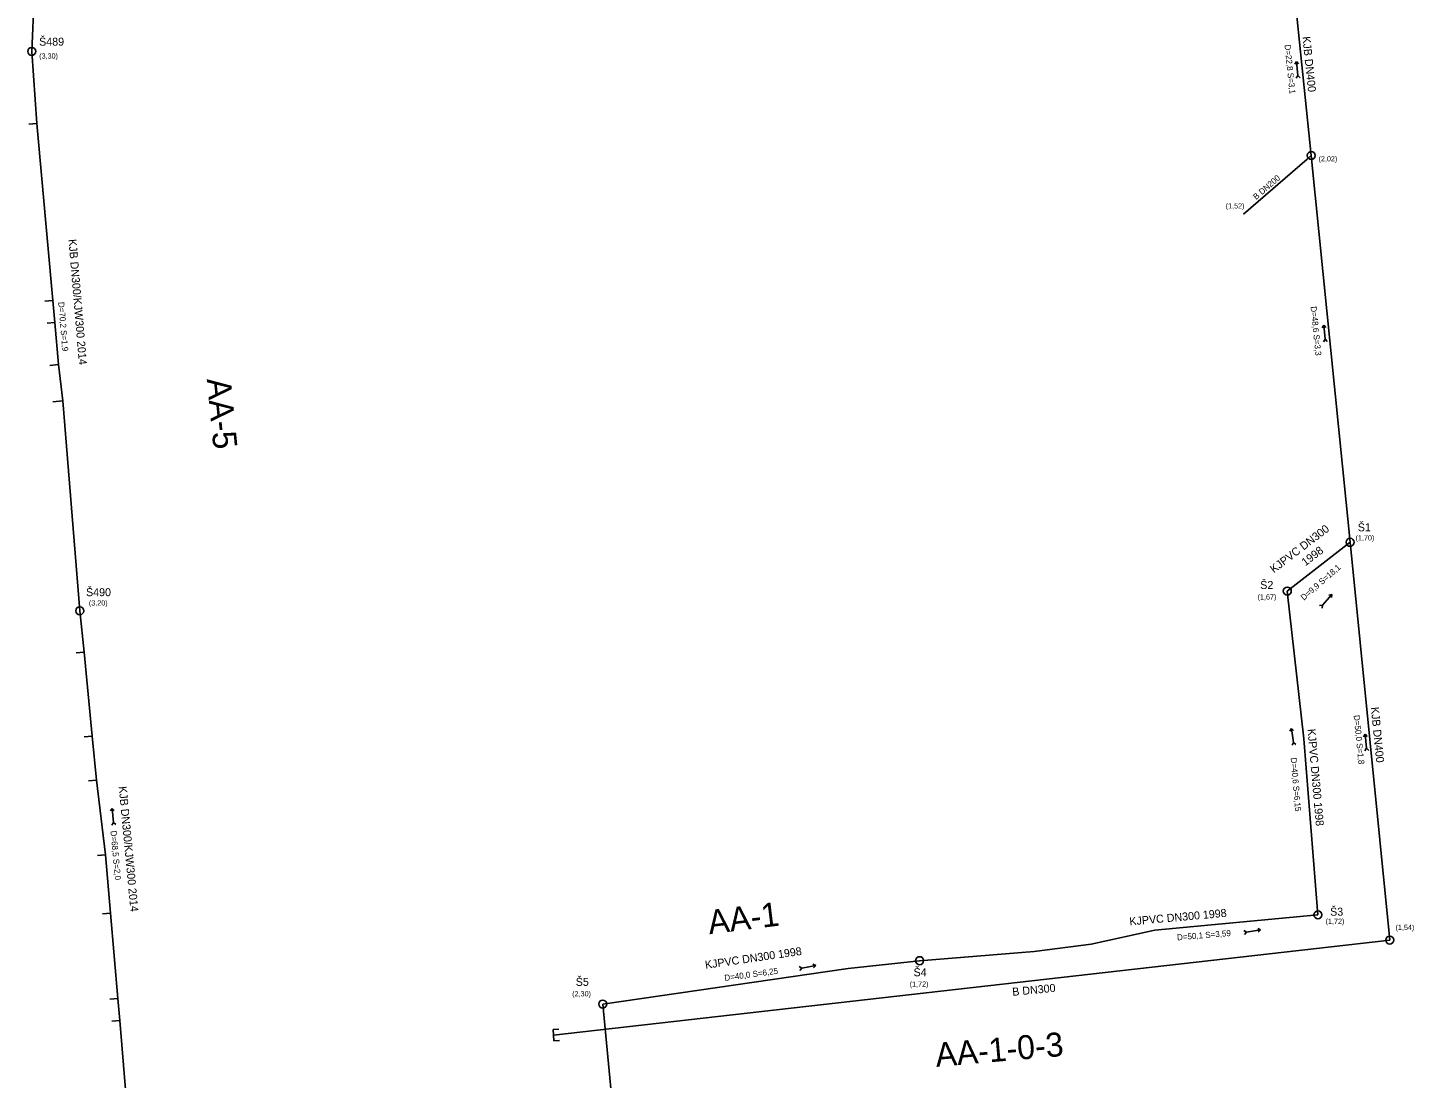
# Model space of a CAD drawing. Extents: x -539706 to -539225, y -1156458 to -1155912.
# Drawn here: x -539640.2 to -539467, y -1156258.9 to -1156127.6 of the extents above; entities that cross this region are included whole.
import ezdxf

# ---------------------------------------------------------------- set-up
doc = ezdxf.new("R2010")
doc.units = 0
for name, color, linetype in [('Vrstva 17', 7, 'Continuous'), ('Vrstva 23', 7, 'Continuous'), ('Vrstva 29', 7, 'Continuous'), ('Vrstva 39', 7, 'Continuous'), ('Vrstva 42', 7, 'Continuous'), ('Vrstva 46', 7, 'Continuous'), ('Vrstva 54', 7, 'Continuous'), ('Vrstva 57', 7, 'Continuous'), ('Vrstva 59', 7, 'Continuous'), ('Vrstva 60', 7, 'Continuous'), ('Vrstva 7', 7, 'Continuous'), ('Vrstva 8', 7, 'Continuous'), ('Vrstva 9', 7, 'Continuous')]:
    doc.layers.add(name, color=color, linetype=linetype)

msp = doc.modelspace()

# ---------------------------------------------------------------- linework, layer by layer
at = {"layer": 'Vrstva 17'}
for p, q in [((-539639.07, -1156139.54), (-539640.07, -1156139.62)), ((-539480.299, -1156144), (-539479.78, -1156143.55)), ((-539488.26, -1156150.9), (-539480.299, -1156144)), ((-539637.06, -1156161.68), (-539638.057, -1156161.764)), ((-539636.81, -1156164.42), (-539637.744, -1156164.497)), ((-539636.33, -1156169.69), (-539637.425, -1156169.783)), ((-539635.81, -1156174.22), (-539637.041, -1156174.324)), ((-539633.15, -1156205.63), (-539634.146, -1156205.714)), ((-539632.14, -1156216.11), (-539633.136, -1156216.194)), ((-539631.6, -1156221.64), (-539632.596, -1156221.724)), ((-539630.46, -1156230.94), (-539631.456, -1156231.024)), ((-539629.84, -1156238.25), (-539630.836, -1156238.334)), ((-539628.93, -1156248.9), (-539629.926, -1156248.984)), ((-539628.69, -1156251.67), (-539629.686, -1156251.754))]:
    msp.add_line(p, q, dxfattribs=at)
at = {"layer": 'Vrstva 23'}
msp.add_line((-539574.481, -1156253.5), (-539469.97, -1156241.61), dxfattribs=at)
at = {"layer": 'Vrstva 29'}
for centre in [(-539639.69, -1156130.54), (-539479.78, -1156143.55), (-539474.92, -1156191.9), (-539482.77, -1156197.99), (-539633.68, -1156200.46), (-539478.95, -1156238.46), (-539469.97, -1156241.61), (-539528.73, -1156244.19), (-539568.33, -1156249.61)]:
    msp.add_circle(centre, 0.5, dxfattribs=at)
at = {"layer": 'Vrstva 39'}
for p, q in [((-539481.835, -1156132.129), (-539481.634, -1156131.799)), ((-539481.454, -1156133.544), (-539481.634, -1156131.799)), ((-539481.373, -1156132.081), (-539481.634, -1156131.799)), ((-539481.658, -1156133.879), (-539481.454, -1156133.544)), ((-539481.184, -1156133.83), (-539481.454, -1156133.544)), ((-539478.427, -1156165.102), (-539478.225, -1156164.773)), ((-539478.052, -1156166.518), (-539478.225, -1156164.773)), ((-539477.966, -1156165.055), (-539478.225, -1156164.773)), ((-539478.257, -1156166.852), (-539478.052, -1156166.518)), ((-539477.783, -1156166.806), (-539478.052, -1156166.518)), ((-539478.382, -1156199.742), (-539477.214, -1156198.434)), ((-539477.593, -1156198.507), (-539477.214, -1156198.434)), ((-539477.246, -1156198.816), (-539477.214, -1156198.434)), ((-539478.767, -1156199.816), (-539478.382, -1156199.742)), ((-539478.412, -1156200.134), (-539478.382, -1156199.742)), ((-539482.438, -1156215.509), (-539482.255, -1156215.169)), ((-539481.982, -1156216.902), (-539482.255, -1156215.169)), ((-539481.979, -1156215.437), (-539482.255, -1156215.169)), ((-539473.24, -1156216.21), (-539473.037, -1156215.882)), ((-539472.865, -1156217.627), (-539473.037, -1156215.882)), ((-539472.778, -1156216.164), (-539473.037, -1156215.882)), ((-539482.168, -1156217.247), (-539481.982, -1156216.902)), ((-539481.697, -1156217.174), (-539481.982, -1156216.902)), ((-539473.071, -1156217.961), (-539472.865, -1156217.627)), ((-539472.597, -1156217.915), (-539472.865, -1156217.627)), ((-539629.829, -1156225.48), (-539629.625, -1156225.152)), ((-539629.462, -1156226.899), (-539629.625, -1156225.152)), ((-539629.368, -1156225.436), (-539629.625, -1156225.152)), ((-539629.67, -1156227.232), (-539629.462, -1156226.899)), ((-539629.195, -1156227.188), (-539629.462, -1156226.899)), ((-539488.207, -1156240.438), (-539487.86, -1156240.622)), ((-539487.86, -1156240.622), (-539486.129, -1156240.338)), ((-539486.471, -1156240.157), (-539486.129, -1156240.338)), ((-539486.395, -1156240.615), (-539486.129, -1156240.338)), ((-539488.13, -1156240.909), (-539487.86, -1156240.622)), ((-539543.79, -1156244.931), (-539543.44, -1156245.108)), ((-539543.704, -1156245.4), (-539543.44, -1156245.108)), ((-539543.44, -1156245.108), (-539541.715, -1156244.788)), ((-539542.06, -1156244.614), (-539541.715, -1156244.788)), ((-539541.975, -1156245.07), (-539541.715, -1156244.788))]:
    msp.add_line(p, q, dxfattribs=at)
at = {"layer": 'Vrstva 42'}
for p, q in [((-539574.532, -1156252.796), (-539573.829, -1156252.746)), ((-539574.43, -1156254.204), (-539574.532, -1156252.796)), ((-539574.43, -1156254.204), (-539573.727, -1156254.155))]:
    msp.add_line(p, q, dxfattribs=at)
at = {"layer": 'Vrstva 8'}
for p, q in [((-539639.69, -1156130.54), (-539639.27, -1156120.87)), ((-539639.07, -1156139.54), (-539639.69, -1156130.54)), ((-539637.06, -1156161.68), (-539639.07, -1156139.54)), ((-539636.81, -1156164.42), (-539637.06, -1156161.68)), ((-539636.33, -1156169.69), (-539636.81, -1156164.42)), ((-539635.81, -1156174.22), (-539636.33, -1156169.69)), ((-539633.68, -1156200.46), (-539635.81, -1156174.22)), ((-539482.77, -1156197.99), (-539474.92, -1156191.9)), ((-539633.15, -1156205.63), (-539633.68, -1156200.46)), ((-539632.14, -1156216.11), (-539633.15, -1156205.63)), ((-539631.6, -1156221.64), (-539632.14, -1156216.11)), ((-539630.46, -1156230.94), (-539631.6, -1156221.64)), ((-539629.84, -1156238.25), (-539630.46, -1156230.94)), ((-539628.93, -1156248.9), (-539629.84, -1156238.25)), ((-539628.69, -1156251.67), (-539628.93, -1156248.9)), ((-539561.93, -1156316.27), (-539568.33, -1156249.61)), ((-539627.96, -1156260.31), (-539628.69, -1156251.67))]:
    msp.add_line(p, q, dxfattribs=at)
for points in [[(-539478.95, -1156238.46), (-539480.72, -1156216.45), (-539482.77, -1156197.99)], [(-539528.73, -1156244.19), (-539514.39, -1156243.05), (-539507.3, -1156242.14), (-539499.31, -1156240.36), (-539478.95, -1156238.46)], [(-539568.33, -1156249.61), (-539537.65, -1156245.15), (-539528.73, -1156244.19)]]:
    msp.add_lwpolyline(points, dxfattribs=at)
at = {"layer": 'Vrstva 9'}
for p, q in [((-539479.78, -1156143.55), (-539482.14, -1156120.87)), ((-539474.92, -1156191.9), (-539479.78, -1156143.55)), ((-539469.97, -1156241.61), (-539474.92, -1156191.9))]:
    msp.add_line(p, q, dxfattribs=at)

# ---------------------------------------------------------------- texts
at = {"layer": 'Vrstva 46'}
msp.add_text('B DN200 ', height=0.75, rotation=40.9163, dxfattribs=at).set_placement((-539486.66, -1156149.133))
at = {"layer": 'Vrstva 54'}
for s, rotation, p in [('D=22,8 S=3,1', 275.94061, (-539483.118, -1156129.73)), ('D=70,2 S=1,9', 274.83959, (-539636.372, -1156161.885)), ('D=48,6 S=3,3', 275.73993, (-539479.869, -1156162.439)), ('D=9,9 S=18,1', 41.0277, (-539480.705, -1156199.21)), ('D=50,0 S=1,8', 275.68663, (-539474.482, -1156213.521)), ('D=40,6 S=6,15', 274.8493, (-539482.352, -1156218.844)), ('D=68,5 S=2,0', 275.40109, (-539629.851, -1156227.979)), ('D=50,1 S=3,59', 4.72488, (-539496.525, -1156241.656)), ('D=40,0 S=6,25', 7.61416, (-539553.07, -1156246.717))]:
    msp.add_text(s, height=0.75, rotation=rotation, dxfattribs=at).set_placement(p)
at = {"layer": 'Vrstva 57'}
for s, p in [('Š489', (-539638.769, -1156129.818)), ('Š1', (-539473.966, -1156190.523)), ('Š2', (-539486.156, -1156197.737)), ('Š490', (-539632.904, -1156198.633)), ('Š3', (-539477.427, -1156238.566)), ('Š4', (-539529.482, -1156246.137)), ('Š5', (-539571.7, -1156247.338))]:
    msp.add_text(s, height=1, dxfattribs=at).set_placement(p)
at = {"layer": 'Vrstva 59'}
for s, p in [('(3,30)', (-539638.756, -1156131.436)), ('(2,02)', (-539478.868, -1156144.286)), ('(1,52)', (-539490.473, -1156150.17)), ('(1,70)', (-539474.245, -1156191.662)), ('(1,67) ', (-539486.487, -1156199.051)), ('(3,20)', (-539632.546, -1156199.795)), ('(1,72) ', (-539477.983, -1156239.588)), ('(1,54)', (-539469.245, -1156240.355)), ('(1,72) ', (-539529.965, -1156247.443)), ('(2,30) ', (-539572.143, -1156248.651))]:
    msp.add_text(s, height=0.65, dxfattribs=at).set_placement(p)
at = {"layer": 'Vrstva 60'}
for s, rotation, p in [('AA-5', 275.63069, (-539617.82, -1156171.496)), ('AA-1', 7.03914, (-539554.996, -1156240.89)), ('AA-1-0-3', 4.94698, (-539526.635, -1156257.473))]:
    msp.add_text(s, height=3, rotation=rotation, dxfattribs=at).set_placement(p)
at = {"layer": 'Vrstva 7'}
for s, rotation, p in [('KJB DN400', 275.93951, (-539480.891, -1156128.712)), ('KJB DN300/KJW300 2014', 274.83858, (-539635.105, -1156154.043)), ('KJPVC DN300', 37.47763, (-539484.45, -1156195.789)), ('1998', 37.47763, (-539480.52, -1156194.918)), ('KJB DN400', 275.68646, (-539472.338, -1156212.528)), ('KJPVC DN300 1998', 275.0229, (-539480.258, -1156215.256)), ('KJB DN300/KJW300 2014', 275.3996, (-539628.819, -1156222.434)), ('KJPVC DN300 1998', 5.10832, (-539502.461, -1156239.785)), ('KJPVC DN300 1998', 8.27217, (-539555.464, -1156245.216)), ('B DN300', 5.51124, (-539517.099, -1156248.591))]:
    msp.add_text(s, height=1, rotation=rotation, dxfattribs=at).set_placement(p)

doc.saveas('drawing.dxf')
